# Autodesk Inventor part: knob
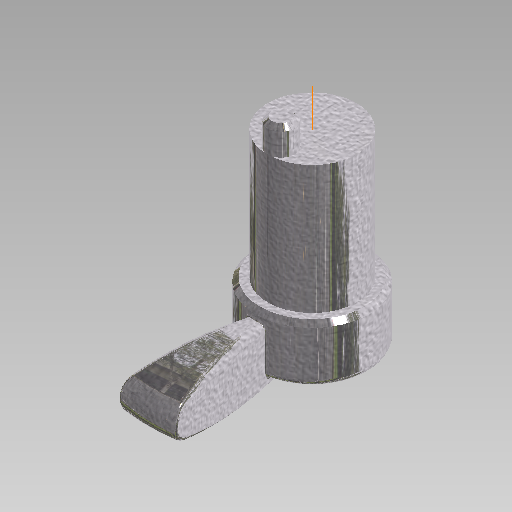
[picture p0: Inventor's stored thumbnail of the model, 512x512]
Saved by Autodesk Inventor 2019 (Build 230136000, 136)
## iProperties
Created: 2000-03
Part Number: knob
Project: 9907-000-182
Document SubType Name: Modeling
Designer: Peter Roberts
Density: 8.47 g/cm^3
Material: Brass, Soft Yellow Brass
Appearance: Aluminium (glänzend)
Manager: Dave Ford
Company: Autodesk Inc.
Control State: 0
Checked Out: False
Master: False
Shininess: 0.0
Length Units: 11269
Angle Units: 11279
Time Units: 11290
Mass Units: 11284
Length Display Precision: 1
Angle Display Precision: 1
Compacted: True
PropertySet Name: Model Information
Density: 0.0
Volumn: 0.0
Area: 0.0
Title: Valve Actuator
Subject: Tutorial #3 part file
Author: Peter Roberts
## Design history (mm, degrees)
node "y-z Plane"
  node "x-z Plane"
  node "x-y Plane"
node "Extrusion1" dims "d0" = 12.7, "d1" = 0
node "Extrusion2" dims "d2" = 28.75006, "d3" = 0
node "Extrusion3" dims "d26" = 6, "d27" = 0
  sketch "Sketch5"
    geometry: C1 r 10 at (0, 0) reference; C2 r 3 at (0, -7)
    constraints: 1 centre point, 1 tangent
    dimensions: "d25" = 6 diameter of C2
node "Chamfer1" dims "d28" = 1, "d29" = 1, "d30" = 45 deg
node "Chamfer2" dims "d8" = 1, "d9" = 1, "d31" = 45 deg
node "Revolution1" dims "d10" = 20 deg
  sketch "Sketch4"
    geometry: L1 (0, 12.7)-(0, -16.898); A1 r 3.964 centre (-33.975, 7.901) between (-35.021, 11.725) and (-35.176, 4.123); A2 r 54.6 centre (-18.644, 56.161) between (-35.176, 4.123) and (0, 4.842); A3 r 66.365 centre (-17.524, -52.291) between (0, 11.718) and (-35.021, 11.725); 2 further points; 1 other entity
    constraints: 6 point on circle, 3 centre point, 2 end point, 2 point on line, 2 tangent, 1 vertical, 2 other
node "Fillet3" dims "d17" = 2, "d18" = 0.025
node "Fillet4" dims "d19" = 0.025, "d20" = 1.5
node "Fillet5" dims "d21" = 1.524
node "Fillet6" dims "d22" = 0.5
workaxis "Work Axis1"
node "Volumenkörper1"
node "Volumenkörpern"
node "Oberflächenkörpern"
sketch "Sketch1"
  geometry: C1 r 12.7 at (0, 0) reference
sketch "Sketch2"
  geometry: C1 r 12.7 at (0, 0) reference; C2 r 10 at (0, 0)
  constraints: 1 centre point, 1 coincident
  dimensions: "d23" = 20 diameter of C2
